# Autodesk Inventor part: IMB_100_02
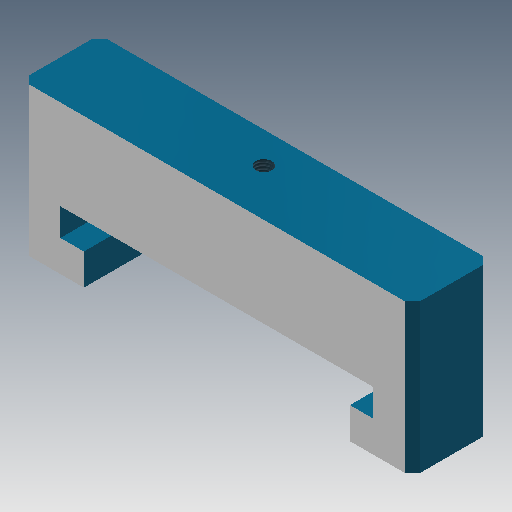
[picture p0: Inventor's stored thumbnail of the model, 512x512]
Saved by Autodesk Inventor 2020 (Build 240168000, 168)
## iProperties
Created: 2011-02
Part Number: IMB_100_02
Document SubType Name: Modeling
Designer: F.Stasiak
Density: 2.71 g/cm^3
Material: Aluminium-6061
Mass: 258.209 g
Surface Area: 169.72 cm^2
Volume: 95.28 cm^3
Description: Docisk
Appearance: Ciemnobłękitna
Manager: www.cadconsulting.pl
Company: Fabian Stasiak CAD Consulting
Author: F.Stasiak
Subject: Zbiór ćwiczeń. Autodesk Inventor 2020. Kurs podstawowy
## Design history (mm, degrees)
sketch "Szkic1"
  geometry: L1 (-50, 0)-(50, 0); L2 (50, 0)-(50, -38); L3 (50, -38)-(34, -38); L4 (34, -38)-(34, -30); L5 (34, -30)-(40, -30); L6 (40, -30)-(40, -23); L7 (40, -23)-(-40, -23); L8 (-40, -23)-(-40, -30); L9 (-40, -30)-(-34, -30); L10 (-34, -30)-(-34, -38); L11 (-34, -38)-(-50, -38); L12 (-50, -38)-(-50, 0); L13 (0, 0)-(0, -23); 1 further point
  constraints: 26 end point, 6 perpendicular, 5 parallel, 2 collinear, 2 midpoint, 1 coincident, 1 horizontal, 1 vertical, 1 other
  dimensions: "d0" = 100 distance of L1.start L1.end; "d1" = 8 distance of L9.end L10.end; "d2" = 7 distance of L7.end L8.end; "d4" = 38 distance between parallel lines of L1 L11; "d27" = 80 distance between parallel lines of L6 L8; "d29" = 68 distance between parallel lines of L4 L10
extrude "Wyciągnięcie proste1" new body sketch "Szkic1" distance "d6" = 20; taper "d7" = 0 deg
sketch "Szkic2"
  geometry: L1 (-40, -23)-(40, -23) reference; L2 (0, 0)-(0, -23); 1 further point
  constraints: 2 end point, 2 midpoint
hole "Hole1" sketch "Szkic2" at (0, -11.5) diameter "d11" = 6.5; stored, may be unused: countersink angle "d15" = 90 deg, drill point angle "d17" = 118 deg; dims "d12" = 6, "d13" = 11, "d14" = 5, "d16" = 15
hole "Hole2" diameter "d20" = 4.134; stored, may be unused: countersink angle "d24" = 90 deg, drill point angle "d26" = 118 deg; dims "d18" = 50 (= 0.5 x d0), "d19" = 8, "d21" = 6, "d22" = 15, "d23" = 10, "d25" = 13.5
chamfer "Faza1" distance "d8" = 2; stored, may be unused: second distance "d9" = 2, angle "d10" = 45 deg
node "Bryła1"
